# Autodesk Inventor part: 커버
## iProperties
Company: 한국ATC센터
Created: 2014-10
Part Number: 커버
Document SubType Name: Modeling
Designer: 한국ATC센터
Density: 2.71 g/cm^3
Material: 알루미늄-6061
Mass: 189.969 g
Surface Area: 197.235 cm^2
Volume: 70.0991 cm^3
Author: KYOUNG IL JANG
